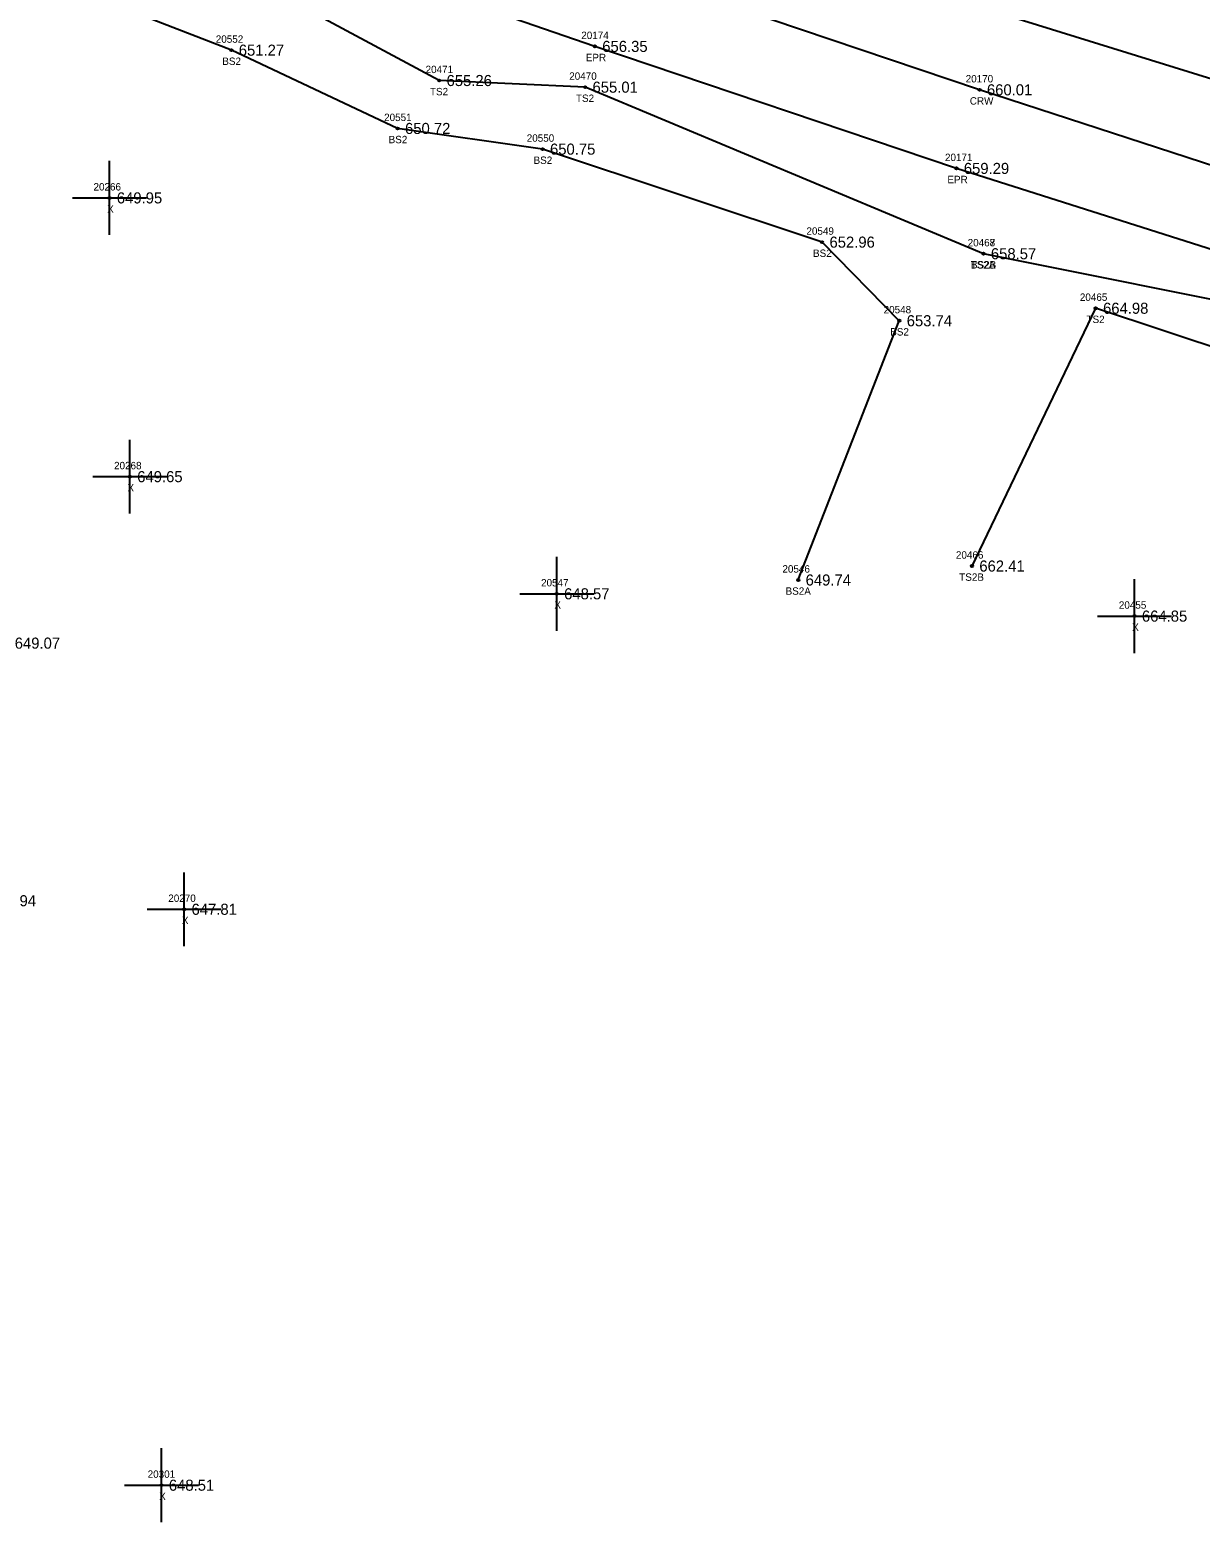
# Model space of a CAD drawing. Extents: x 1655675 to 1657082, y 1004080 to 1005193.
# Drawn here: x 1656397.9 to 1656556.3, y 1004380.5 to 1004582.5 of the extents above; entities that cross this region are included whole.
import ezdxf

# ---------------------------------------------------------------- set-up
doc = ezdxf.new("R2010")
doc.units = 0
for name, color, linetype in [('RD_DTM_BkLn1', 7, 'Continuous'), ('RD_DTM_BkLn2', 7, 'Continuous'), ('RD_DTM_BkLn_txCode', 7, 'Continuous'), ('RD_EX_Misc', 7, 'Continuous'), ('RD_EX_Misc_txCode', 7, 'Continuous'), ('RD_EX_Road', 7, 'Continuous'), ('RD_EX_Road_txCode', 7, 'Continuous'), ('RD_EX_TX_H2O_ELEV', 7, 'Continuous'), ('RD_EX_TX_Misc_ELEV', 7, 'Continuous'), ('RD_EX_TX_Road_ELEV', 7, 'Continuous'), ('RD_HC_Survey_ELEV', 7, 'Continuous'), ('RD_HC_Survey_txCode', 7, 'Continuous'), ('RD_SMD_Locator', 7, 'Continuous')]:
    doc.layers.add(name, color=color, linetype=linetype)

msp = doc.modelspace()

# ---------------------------------------------------------------- linework, layer by layer
at = {"layer": 'RD_DTM_BkLn1'}
msp.add_lwpolyline([(1657061.44, 1004399.53), (1657012.07, 1004414.01), (1656963.11, 1004429.39), (1656914.21, 1004444.93), (1656865.73, 1004460.97), (1656817.07, 1004476.94), (1656768.62, 1004493.15), (1656720.24, 1004509.39), (1656671.72, 1004525.86), (1656623.45, 1004542.51), (1656574.61, 1004558.72), (1656526.43, 1004574.41), (1656478.09, 1004590.75), (1656429.6, 1004607.09), (1656401.58, 1004616.48)], dxfattribs=at)
at = {"layer": 'RD_DTM_BkLn2'}
for points in [[(1656526.96, 1004552.22), (1656473.05, 1004574.77), (1656453.3, 1004575.67), (1656421.97, 1004592.49), (1656400.71, 1004598.65), (1656398.02, 1004604.64)], [(1656501.89, 1004508.05), (1656515.57, 1004543.15), (1656505.12, 1004553.79), (1656467.3, 1004566.38), (1656447.68, 1004569.18), (1656425.18, 1004579.78), (1656399.76, 1004589.64), (1656384.32, 1004599.06)], [(1656916.22, 1004427.16), (1656860.73, 1004444.79), (1656812.26, 1004457.45), (1656804.38, 1004456.52), (1656762.93, 1004472.17), (1656714, 1004488.45), (1656666.66, 1004507.38), (1656620.12, 1004527.68), (1656568.41, 1004543.92), (1656526.96, 1004552.22)], [(1656877.14, 1004434.43), (1656862.63, 1004439.86), (1656832.96, 1004433.22), (1656804.97, 1004442.37), (1656761.39, 1004459.38), (1656711.4, 1004477.11), (1656669.22, 1004500.61), (1656617.04, 1004520), (1656542.14, 1004544.84), (1656525.4, 1004509.94)]]:
    msp.add_lwpolyline(points, dxfattribs=at)
at = {"layer": 'RD_EX_Misc'}
for p, q in [((1656408.68, 1004554.78), (1656408.68, 1004564.78)), ((1656403.68, 1004559.78), (1656413.68, 1004559.78)), ((1656411.44, 1004517.04), (1656411.44, 1004527.04)), ((1656406.44, 1004522.04), (1656416.44, 1004522.04)), ((1656469.21, 1004501.18), (1656469.21, 1004511.18)), ((1656547.4, 1004498.16), (1656547.4, 1004508.16)), ((1656464.21, 1004506.18), (1656474.21, 1004506.18)), ((1656542.4, 1004503.16), (1656552.4, 1004503.16)), ((1656418.79, 1004458.47), (1656418.79, 1004468.47)), ((1656413.79, 1004463.47), (1656423.79, 1004463.47)), ((1656415.72, 1004380.5), (1656415.72, 1004390.5)), ((1656410.72, 1004385.5), (1656420.72, 1004385.5))]:
    msp.add_line(p, q, dxfattribs=at)
at = {"layer": 'RD_EX_Road'}
for points in [[(1657064.39, 1004409.09), (1657015.67, 1004424.64), (1656965.82, 1004440.6), (1656917.99, 1004455.95), (1656868.5, 1004471.86), (1656826.53, 1004486.06), (1656801.74, 1004494.51), (1656772.14, 1004504.27), (1656723.45, 1004520.92), (1656674.94, 1004537.34), (1656626.5, 1004553.88), (1656578.27, 1004569.52), (1656529.18, 1004584.75), (1656481.5, 1004600.51), (1656432.67, 1004617.14), (1656404.34, 1004625.82)], [(1657057.77, 1004388.92), (1657009.7, 1004404.08), (1656958.18, 1004419.84), (1656956.49, 1004419.67), (1656924.83, 1004429.55), (1656916.51, 1004432.8), (1656911.19, 1004434.68), (1656862.46, 1004450.21), (1656813.53, 1004466.42), (1656765.51, 1004482.33), (1656716.81, 1004499.14), (1656668.6, 1004515.93), (1656620.24, 1004532.54), (1656571.72, 1004548.37), (1656523.3, 1004563.77), (1656474.37, 1004580.29), (1656426.43, 1004596.82), (1656398.22, 1004606.78)]]:
    msp.add_lwpolyline(points, dxfattribs=at)
at = {"layer": 'RD_SMD_Locator'}
for centre in [(1656474.37, 1004580.29), (1656425.18, 1004579.78), (1656453.3, 1004575.67), (1656473.05, 1004574.77), (1656526.43, 1004574.41), (1656447.68, 1004569.18), (1656467.3, 1004566.38), (1656523.3, 1004563.77), (1656408.68, 1004559.78), (1656505.12, 1004553.79), (1656526.96, 1004552.22), (1656526.96, 1004552.22), (1656542.14, 1004544.84), (1656515.57, 1004543.15), (1656411.44, 1004522.04), (1656525.4, 1004509.94), (1656501.89, 1004508.05), (1656469.21, 1004506.18), (1656547.4, 1004503.16), (1656418.79, 1004463.47), (1656415.72, 1004385.5)]:
    msp.add_circle(centre, 0.15, dxfattribs=at)

# ---------------------------------------------------------------- texts
at = {"layer": 'RD_DTM_BkLn_txCode'}
for s, p in [('20552', (1656423.07, 1004580.78)), ('BS2', (1656423.95, 1004577.78)), ('20471', (1656451.46, 1004576.67)), ('20470', (1656470.9, 1004575.77)), ('TS2', (1656452.05, 1004573.67)), ('TS2', (1656471.81, 1004572.77)), ('20551', (1656445.85, 1004570.18)), ('BS2', (1656446.46, 1004567.18)), ('20550', (1656465.15, 1004567.38)), ('BS2', (1656466.07, 1004564.38)), ('20549', (1656503, 1004554.79)), ('20467', (1656524.82, 1004553.22)), ('20468', (1656524.82, 1004553.22)), ('BS2', (1656503.89, 1004551.79)), ('TS2A', (1656525.23, 1004550.22)), ('BS2B', (1656525.26, 1004550.22)), ('20465', (1656540, 1004545.84)), ('20548', (1656513.45, 1004544.15)), ('BS2', (1656514.34, 1004541.15)), ('TS2', (1656540.9, 1004542.84)), ('20466', (1656523.23, 1004510.94)), ('20546', (1656499.75, 1004509.05)), ('TS2B', (1656523.68, 1004507.94)), ('BS2A', (1656500.18, 1004506.05))]:
    msp.add_text(s, height=1, dxfattribs=at).set_placement(p)
at = {"layer": 'RD_EX_Misc_txCode'}
for s, p in [('20266', (1656406.52, 1004560.78)), ('X', (1656408.37, 1004557.78)), ('20268', (1656409.3, 1004523.04)), ('X', (1656411.12, 1004520.04)), ('20547', (1656467.09, 1004507.18)), ('X', (1656468.89, 1004504.18)), ('20455', (1656545.28, 1004504.16)), ('X', (1656547.08, 1004501.16)), ('20270', (1656416.64, 1004464.47)), ('X', (1656418.48, 1004461.47)), ('20301', (1656413.85, 1004386.5)), ('X', (1656415.41, 1004383.5))]:
    msp.add_text(s, height=1, dxfattribs=at).set_placement(p)
at = {"layer": 'RD_EX_Road_txCode'}
for s, p in [('20174', (1656472.53, 1004581.29)), ('EPR', (1656473.14, 1004578.29)), ('20171', (1656521.75, 1004564.77)), ('EPR', (1656522.08, 1004561.77))]:
    msp.add_text(s, height=1, dxfattribs=at).set_placement(p)
at = {"layer": 'RD_EX_TX_H2O_ELEV'}
for s, p in [('649.07', (1656395.86, 1004498.75)), ('647.94', (1656392.61, 1004463.88))]:
    msp.add_text(s, height=1.5, dxfattribs=at).set_placement(p)
at = {"layer": 'RD_EX_TX_Misc_ELEV'}
for s, p in [('651.27', (1656426.18, 1004579.03)), ('655.26', (1656454.3, 1004574.92)), ('655.01', (1656474.05, 1004574.02)), ('650.72', (1656448.68, 1004568.43)), ('650.75', (1656468.3, 1004565.63)), ('649.95', (1656409.68, 1004559.03)), ('652.96', (1656506.12, 1004553.04)), ('658.57', (1656527.96, 1004551.47)), ('658.57', (1656527.96, 1004551.47)), ('653.74', (1656516.57, 1004542.4)), ('664.98', (1656543.14, 1004544.09)), ('649.65', (1656412.44, 1004521.29)), ('662.41', (1656526.4, 1004509.19)), ('649.74', (1656502.89, 1004507.3)), ('648.57', (1656470.21, 1004505.43)), ('664.85', (1656548.4, 1004502.41)), ('647.81', (1656419.79, 1004462.72)), ('648.51', (1656416.72, 1004384.75))]:
    msp.add_text(s, height=1.5, dxfattribs=at).set_placement(p)
at = {"layer": 'RD_EX_TX_Road_ELEV'}
for s, p in [('656.35', (1656475.37, 1004579.54)), ('659.29', (1656524.3, 1004563.02))]:
    msp.add_text(s, height=1.5, dxfattribs=at).set_placement(p)
at = {"layer": 'RD_HC_Survey_ELEV'}
msp.add_text('660.01', height=1.5, dxfattribs=at).set_placement((1656527.43, 1004573.66))
at = {"layer": 'RD_HC_Survey_txCode'}
for s, p in [('20170', (1656524.55, 1004575.41)), ('CRW', (1656525.11, 1004572.41))]:
    msp.add_text(s, height=1, dxfattribs=at).set_placement(p)

doc.saveas('drawing.dxf')
